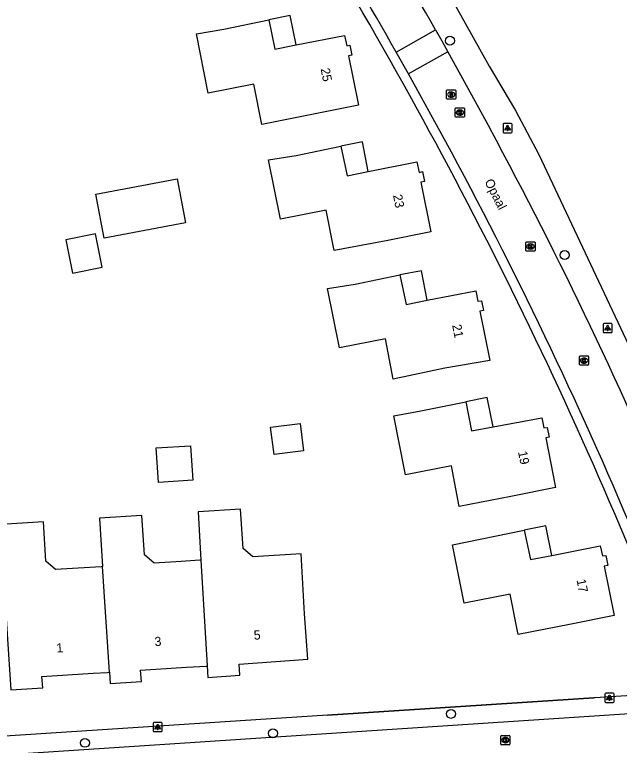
# Model space of a CAD drawing. Extents: x 159628 to 160723, y 388176 to 389416.
# Drawn here: x 160613.8 to 160680, y 388506.9 to 388586.9 of the extents above; entities that cross this region are included whole.
import ezdxf

# ---------------------------------------------------------------- set-up
doc = ezdxf.new("R2010")
doc.units = 0
for name, color, linetype in [('IMGEO_Boom', 7, 'Continuous'), ('IMGEO_Fietspad_gesloten', 7, 'Continuous'), ('IMGEO_Kolk', 7, 'Continuous'), ('IMGEO_Lichtpunt', 7, 'Continuous'), ('IMGEO_Muur', 7, 'Continuous'), ('IMGEO_Openbare_ruimte_label', 7, 'Continuous'), ('IMGEO_Pand', 7, 'Continuous'), ('IMGEO_Pand_nummerreeks', 7, 'Continuous'), ('IMGEO_Pand_overbouw', 7, 'Continuous'), ('IMGEO_Rijbaan_lokaal_open', 7, 'Continuous'), ('IMGEO_Rioolput', 7, 'Continuous'), ('IMGEO_Voetpad_open', 7, 'Continuous')]:
    doc.layers.add(name, color=color, linetype=linetype)

msp = doc.modelspace()

# ---------------------------------------------------------------- linework, layer by layer
at = {"layer": 'IMGEO_Boom'}
for centre in [(160661.403, 388584.05), (160673.966, 388560.586), (160661.517, 388510.38), (160642.034, 388508.252), (160621.458, 388507.209)]:
    msp.add_circle(centre, 0.489, dxfattribs=at)
at = {"layer": 'IMGEO_Fietspad_gesloten'}
msp.add_lwpolyline([(160617.404, 388655.77), (160618.348, 388654.532), (160644.11, 388617.805), (160648.439, 388610.479), (160651.047, 388606.571), (160653.72, 388602.158), (160659.741, 388591.966), (160665.707, 388581.259), (160668.575, 388576.406), (160671.137, 388571.605), (160689.88, 388531.792), (160696.248, 388516.722), (160696.73, 388515.639)], dxfattribs=at)
at = {"layer": 'IMGEO_Kolk'}
for p, q in [((160661.995, 388575.76), (160661.995, 388576.612)), ((160662.07, 388576.686), (160662.922, 388576.686)), ((160662.483, 388576.466), (160662.508, 388576.466)), ((160662.996, 388576.612), (160662.996, 388575.76)), ((160662.922, 388575.686), (160662.07, 388575.686)), ((160662.506, 388575.906), (160662.481, 388575.906)), ((160669.721, 388561.098), (160669.721, 388561.95)), ((160669.796, 388562.024), (160670.648, 388562.024)), ((160670.722, 388561.95), (160670.722, 388561.098)), ((160670.232, 388561.244), (160670.207, 388561.244)), ((160670.209, 388561.804), (160670.234, 388561.804)), ((160670.648, 388561.024), (160669.796, 388561.024)), ((160675.585, 388548.618), (160675.585, 388549.47)), ((160675.66, 388549.544), (160676.512, 388549.544)), ((160676.073, 388549.324), (160676.098, 388549.324)), ((160676.586, 388549.47), (160676.586, 388548.618)), ((160676.512, 388548.544), (160675.66, 388548.544)), ((160676.096, 388548.764), (160676.071, 388548.764)), ((160666.966, 388507.082), (160666.966, 388507.934)), ((160667.041, 388508.008), (160667.893, 388508.008)), ((160667.454, 388507.788), (160667.479, 388507.788)), ((160667.967, 388507.934), (160667.967, 388507.082)), ((160667.893, 388507.008), (160667.041, 388507.008)), ((160667.477, 388507.228), (160667.452, 388507.228))]:
    msp.add_line(p, q, dxfattribs=at)
for points in [[(160661.995, 388575.76), (160661.995, 388576.612)], [(160662.07, 388576.686), (160662.922, 388576.686)], [(160662.316, 388576.386), (160662.439, 388576.386), (160662.439, 388576.235), (160662.569, 388576.386), (160662.733, 388576.386), (160662.587, 388576.235), (160662.74, 388575.986), (160662.588, 388575.986), (160662.503, 388576.15), (160662.439, 388576.083), (160662.439, 388575.986), (160662.316, 388575.986), (160662.316, 388576.386)], [(160662.996, 388576.612), (160662.996, 388575.76)], [(160662.922, 388575.686), (160662.07, 388575.686)], [(160669.721, 388561.098), (160669.721, 388561.95)], [(160669.796, 388562.024), (160670.648, 388562.024)], [(160670.722, 388561.95), (160670.722, 388561.098)], [(160670.042, 388561.724), (160670.165, 388561.724), (160670.165, 388561.573), (160670.295, 388561.724), (160670.459, 388561.724), (160670.313, 388561.573), (160670.466, 388561.324), (160670.314, 388561.324), (160670.229, 388561.488), (160670.165, 388561.421), (160670.165, 388561.324), (160670.042, 388561.324), (160670.042, 388561.724)], [(160670.648, 388561.024), (160669.796, 388561.024)], [(160675.585, 388548.618), (160675.585, 388549.47)], [(160675.66, 388549.544), (160676.512, 388549.544)], [(160675.906, 388549.244), (160676.029, 388549.244), (160676.029, 388549.093), (160676.159, 388549.244), (160676.323, 388549.244), (160676.177, 388549.093), (160676.33, 388548.844), (160676.178, 388548.844), (160676.093, 388549.008), (160676.029, 388548.941), (160676.029, 388548.844), (160675.906, 388548.844), (160675.906, 388549.244)], [(160676.586, 388549.47), (160676.586, 388548.618)], [(160676.512, 388548.544), (160675.66, 388548.544)], [(160666.966, 388507.082), (160666.966, 388507.934)], [(160667.041, 388508.008), (160667.893, 388508.008)], [(160667.287, 388507.708), (160667.41, 388507.708), (160667.41, 388507.557), (160667.54, 388507.708), (160667.704, 388507.708), (160667.558, 388507.557), (160667.711, 388507.308), (160667.559, 388507.308), (160667.474, 388507.472), (160667.41, 388507.405), (160667.41, 388507.308), (160667.287, 388507.308), (160667.287, 388507.708)], [(160667.967, 388507.934), (160667.967, 388507.082)], [(160667.893, 388507.008), (160667.041, 388507.008)]]:
    msp.add_lwpolyline(points, dxfattribs=at)
for centre, start, end in [((160662.072, 388576.61), 91.55205, 178.44795), ((160662.072, 388576.61), 91.55205, 178.44795), ((160662.92, 388576.61), 1.55205, 88.44795), ((160662.92, 388576.61), 1.55205, 88.44795), ((160662.072, 388575.762), 181.55205, 268.44795), ((160662.072, 388575.762), 181.55205, 268.44795), ((160662.92, 388575.762), 271.55205, 358.44795), ((160662.92, 388575.762), 271.55205, 358.44795), ((160669.798, 388561.948), 91.55205, 178.44795), ((160669.798, 388561.948), 91.55205, 178.44795), ((160670.646, 388561.948), 1.55205, 88.44795), ((160670.646, 388561.948), 1.55205, 88.44795), ((160669.798, 388561.1), 181.55205, 268.44795), ((160669.798, 388561.1), 181.55205, 268.44795), ((160670.646, 388561.1), 271.55205, 358.44795), ((160670.646, 388561.1), 271.55205, 358.44795), ((160675.662, 388549.468), 91.55205, 178.44795), ((160675.662, 388549.468), 91.55205, 178.44795), ((160676.51, 388549.468), 1.55205, 88.44795), ((160676.51, 388549.468), 1.55205, 88.44795), ((160675.662, 388548.62), 181.55205, 268.44795), ((160675.662, 388548.62), 181.55205, 268.44795), ((160676.51, 388548.62), 271.55205, 358.44795), ((160676.51, 388548.62), 271.55205, 358.44795), ((160667.043, 388507.932), 91.55205, 178.44795), ((160667.043, 388507.932), 91.55205, 178.44795), ((160667.891, 388507.932), 1.55205, 88.44795), ((160667.891, 388507.932), 1.55205, 88.44795), ((160667.043, 388507.084), 181.55205, 268.44795), ((160667.043, 388507.084), 181.55205, 268.44795), ((160667.891, 388507.084), 271.55205, 358.44795), ((160667.891, 388507.084), 271.55205, 358.44795)]:
    msp.add_arc(centre, 0.0765, start, end, dxfattribs=at)
for centre, major_axis, ratio, start_param, end_param in [((160662.482, 388576.186), (-0.387, 0.002), 0.722429, 4.712389, 7.853982), ((160662.507, 388576.186), (-0.39, 0.002), 0.717154, 1.570796, 4.712389), ((160670.208, 388561.524), (-0.387, 0.002), 0.722429, 4.712389, 7.853982), ((160670.233, 388561.524), (-0.39, 0.002), 0.717154, 1.570796, 4.712389), ((160676.072, 388549.044), (-0.387, 0.002), 0.722429, 4.712389, 7.853982), ((160676.097, 388549.044), (-0.39, 0.002), 0.717154, 1.570796, 4.712389), ((160667.453, 388507.508), (-0.387, 0.002), 0.722429, 4.712389, 7.853982), ((160667.478, 388507.508), (-0.39, 0.002), 0.717154, 1.570796, 4.712389)]:
    msp.add_ellipse(centre, major_axis=major_axis, ratio=ratio, start_param=start_param, end_param=end_param, dxfattribs=at)
at = {"layer": 'IMGEO_Lichtpunt'}
for p, q in [((160667.216, 388574.882), (160667.216, 388574.075)), ((160667.216, 388574.882), (160667.216, 388574.075)), ((160668.118, 388574.977), (160667.31, 388574.977)), ((160668.118, 388574.977), (160667.31, 388574.977)), ((160668.212, 388574.075), (160668.212, 388574.882)), ((160668.212, 388574.075), (160668.212, 388574.882)), ((160667.31, 388573.981), (160668.118, 388573.981)), ((160667.31, 388573.981), (160668.118, 388573.981)), ((160679.073, 388553.1), (160678.265, 388553.1)), ((160679.073, 388553.1), (160678.265, 388553.1)), ((160678.171, 388553.005), (160678.171, 388552.198)), ((160678.171, 388553.005), (160678.171, 388552.198)), ((160679.167, 388552.198), (160679.167, 388553.005)), ((160679.167, 388552.198), (160679.167, 388553.005)), ((160678.265, 388552.104), (160679.073, 388552.104)), ((160678.265, 388552.104), (160679.073, 388552.104)), ((160678.367, 388512.533), (160678.367, 388511.726)), ((160678.367, 388512.533), (160678.367, 388511.726)), ((160679.269, 388512.628), (160678.461, 388512.628)), ((160679.269, 388512.628), (160678.461, 388512.628)), ((160679.363, 388511.726), (160679.363, 388512.533)), ((160679.363, 388511.726), (160679.363, 388512.533)), ((160678.461, 388511.632), (160679.269, 388511.632)), ((160678.461, 388511.632), (160679.269, 388511.632)), ((160628.924, 388509.337), (160628.924, 388508.53)), ((160628.924, 388509.337), (160628.924, 388508.53)), ((160629.826, 388509.432), (160629.018, 388509.432)), ((160629.826, 388509.432), (160629.018, 388509.432)), ((160629.92, 388508.53), (160629.92, 388509.337)), ((160629.92, 388508.53), (160629.92, 388509.337)), ((160629.018, 388508.436), (160629.826, 388508.436)), ((160629.018, 388508.436), (160629.826, 388508.436))]:
    msp.add_line(p, q, dxfattribs=at)
for points in [[(160667.59, 388574.546), (160667.629, 388574.518), (160667.441, 388574.256), (160667.403, 388574.283), (160667.59, 388574.546)], [(160667.692, 388574.498), (160667.739, 388574.498), (160667.739, 388574.176), (160667.692, 388574.176), (160667.692, 388574.498)], [(160667.802, 388574.518), (160667.84, 388574.545), (160668.027, 388574.283), (160667.988, 388574.255), (160667.802, 388574.518)], [(160678.545, 388552.669), (160678.584, 388552.641), (160678.396, 388552.379), (160678.358, 388552.406), (160678.545, 388552.669)], [(160678.647, 388552.621), (160678.694, 388552.621), (160678.694, 388552.299), (160678.647, 388552.299), (160678.647, 388552.621)], [(160678.757, 388552.641), (160678.795, 388552.668), (160678.982, 388552.406), (160678.943, 388552.378), (160678.757, 388552.641)], [(160678.741, 388512.197), (160678.78, 388512.169), (160678.592, 388511.907), (160678.554, 388511.934), (160678.741, 388512.197)], [(160678.843, 388512.149), (160678.89, 388512.149), (160678.89, 388511.827), (160678.843, 388511.827), (160678.843, 388512.149)], [(160678.953, 388512.169), (160678.991, 388512.196), (160679.178, 388511.934), (160679.139, 388511.906), (160678.953, 388512.169)], [(160629.298, 388509.001), (160629.337, 388508.973), (160629.149, 388508.711), (160629.111, 388508.738), (160629.298, 388509.001)], [(160629.4, 388508.953), (160629.447, 388508.953), (160629.447, 388508.631), (160629.4, 388508.631), (160629.4, 388508.953)], [(160629.51, 388508.973), (160629.548, 388509), (160629.735, 388508.738), (160629.696, 388508.71), (160629.51, 388508.973)]]:
    msp.add_lwpolyline(points, dxfattribs=at)
for centre in [(160667.715, 388574.68), (160678.67, 388552.803), (160678.866, 388512.331), (160629.423, 388509.135)]:
    msp.add_circle(centre, 0.0994, dxfattribs=at)
for centre, start, end in [((160667.31, 388574.882), 90, 180), ((160667.31, 388574.882), 90, 180), ((160668.118, 388574.882), 0, 90), ((160668.118, 388574.882), 0, 90), ((160667.31, 388574.075), 180, 270), ((160667.31, 388574.075), 180, 270), ((160668.118, 388574.075), 270, 0), ((160668.118, 388574.075), 270, 360), ((160678.265, 388553.005), 90, 180), ((160678.265, 388553.005), 90, 180), ((160679.073, 388553.005), 0, 90), ((160679.073, 388553.005), 0, 90), ((160678.265, 388552.198), 180, 270), ((160678.265, 388552.198), 180, 270), ((160679.073, 388552.198), 270, 0), ((160679.073, 388552.198), 270, 360), ((160678.461, 388512.533), 90, 180), ((160678.461, 388512.533), 90, 180), ((160679.269, 388512.533), 0, 90), ((160679.269, 388512.533), 0, 90), ((160678.461, 388511.726), 180, 270), ((160678.461, 388511.726), 180, 270), ((160679.269, 388511.726), 270, 0), ((160679.269, 388511.726), 270, 360), ((160629.018, 388509.337), 90, 180), ((160629.018, 388509.337), 90, 180), ((160629.826, 388509.337), 0, 90), ((160629.826, 388509.337), 0, 90), ((160629.018, 388508.53), 180, 270), ((160629.018, 388508.53), 180, 270), ((160629.826, 388508.53), 270, 0), ((160629.826, 388508.53), 270, 360)]:
    msp.add_arc(centre, 0.0946, start, end, dxfattribs=at)
at = {"layer": 'IMGEO_Muur'}
msp.add_lwpolyline([(160648.016, 388510.238), (160677.163, 388512.123)], dxfattribs=at)
at = {"layer": 'IMGEO_Pand'}
for points in [[(160646.491, 388576.008), (160640.824, 388574.888), (160639.948, 388579.304), (160634.944, 388578.311), (160633.658, 388584.787), (160636.68, 388585.304), (160641.57, 388586.346), (160642.256, 388583.128), (160644.574, 388583.58), (160649.858, 388584.611), (160650.11, 388583.493), (160650.464, 388583.541), (160650.679, 388582.473), (160650.313, 388582.397), (160651.396, 388576.975), (160646.491, 388576.008)], [(160647.866, 388565.509), (160642.86, 388564.529), (160641.552, 388570.993), (160644.587, 388571.499), (160649.481, 388572.521), (160650.16, 388569.272), (160652.463, 388569.729), (160657.779, 388570.785), (160658.041, 388569.63), (160658.4, 388569.717), (160658.611, 388568.63), (160658.231, 388568.553), (160659.316, 388563.147), (160654.415, 388562.161), (160648.731, 388561.091), (160647.866, 388565.509)], [(160622.659, 388567.255), (160631.546, 388568.935), (160632.458, 388564.104), (160623.572, 388562.425), (160622.659, 388567.255)], [(160620.115, 388558.604), (160623.35, 388559.265), (160622.604, 388562.918), (160619.369, 388562.258), (160620.115, 388558.604)], [(160651.041, 388557.391), (160655.935, 388558.413), (160656.61, 388555.183), (160658.924, 388555.636), (160664.232, 388556.676), (160664.471, 388555.532), (160664.849, 388555.597), (160665.066, 388554.539), (160664.695, 388554.445), (160665.767, 388549.04), (160660.838, 388548.204), (160655.206, 388546.992), (160654.339, 388551.409), (160649.333, 388550.426), (160648.026, 388556.912), (160651.041, 388557.391)], [(160663.133, 388544.528), (160663.774, 388541.342), (160666.14, 388541.789), (160671.449, 388542.791), (160671.682, 388541.68), (160672.047, 388541.73), (160672.258, 388540.651), (160671.895, 388540.574), (160672.975, 388535.152), (160668.072, 388534.173), (160662.427, 388533.091), (160661.562, 388537.51), (160656.553, 388536.53), (160655.285, 388542.99), (160658.232, 388543.542), (160663.133, 388544.528)], [(160641.786, 388541.752), (160645.022, 388542.156), (160645.393, 388539.183), (160642.156, 388538.779), (160641.786, 388541.752)], [(160629.27, 388539.48), (160633.024, 388539.722), (160633.268, 388535.953), (160629.513, 388535.711), (160629.27, 388539.48)], [(160634.833, 388515.62), (160634.906, 388514.366), (160638.418, 388514.61), (160638.339, 388515.837), (160645.838, 388516.351), (160645.497, 388521.34), (160645.131, 388527.893), (160639.827, 388527.554), (160638.765, 388528.488), (160638.491, 388532.785), (160633.851, 388532.484), (160634.159, 388527.193)], [(160634.159, 388527.193), (160634.033, 388527.185), (160631.983, 388527.053), (160629.044, 388526.863), (160627.981, 388527.796), (160627.704, 388532.087), (160623.054, 388531.786), (160623.396, 388526.497)], [(160623.396, 388526.497), (160623.236, 388526.487), (160618.868, 388526.205), (160618.256, 388526.165), (160617.193, 388527.098), (160616.916, 388531.389), (160612.242, 388531.087)], [(160669.546, 388530.489), (160670.211, 388527.262), (160672.57, 388527.729), (160677.854, 388528.775), (160678.092, 388527.68), (160678.458, 388527.701), (160678.678, 388526.63), (160678.293, 388526.549), (160679.386, 388521.137), (160674.482, 388520.155), (160668.857, 388519.051), (160667.991, 388523.484), (160662.967, 388522.502), (160661.691, 388528.87), (160669.546, 388530.489)], [(160634.159, 388527.193), (160634.833, 388515.62)], [(160624.144, 388514.933), (160623.396, 388526.497)], [(160612.793, 388521.346), (160613.018, 388517.996), (160613.348, 388513.006), (160616.84, 388513.237), (160616.735, 388514.453), (160622.367, 388514.818), (160623.943, 388514.92), (160624.144, 388514.933)], [(160624.144, 388514.933), (160624.224, 388513.704), (160627.638, 388513.913), (160627.557, 388515.168), (160632.568, 388515.479), (160634.749, 388515.615), (160634.833, 388515.62)]]:
    msp.add_lwpolyline(points, dxfattribs=at)
at = {"layer": 'IMGEO_Pand_overbouw'}
for points in [[(160644.574, 388583.58), (160643.925, 388586.811), (160641.57, 388586.346), (160642.256, 388583.128)], [(160652.463, 388569.729), (160651.839, 388572.985), (160649.481, 388572.521), (160650.16, 388569.272)], [(160655.935, 388558.413), (160656.61, 388555.183), (160658.924, 388555.636), (160658.288, 388558.879)], [(160666.14, 388541.789), (160665.496, 388544.997), (160663.133, 388544.528), (160663.774, 388541.342)], [(160672.57, 388527.729), (160671.905, 388530.953), (160669.546, 388530.489), (160670.211, 388527.262)]]:
    msp.add_lwpolyline(points, close=True, dxfattribs=at)
at = {"layer": 'IMGEO_Rijbaan_lokaal_open'}
for points in [[(160655.528, 388582.803), (160659.827, 388585.236)], [(160659.827, 388585.236), (160660.507, 388584.03), (160661.184, 388582.823)], [(160656.874, 388580.411), (160655.528, 388582.803)], [(160661.184, 388582.823), (160656.874, 388580.411)], [(160661.184, 388582.823), (160665.773, 388574.47)], [(160661.572, 388571.858), (160656.874, 388580.411)], [(160601.875, 388505.15), (160610.788, 388505.771), (160685.519, 388510.699)]]:
    msp.add_lwpolyline(points, dxfattribs=at)
for centre, radius, start, end in [((160131.083, 388286.162), 607.466, 29.493811, 32.869723), ((160131.433, 388286.289), 602.16, 29.499633, 32.79812), ((160245.588, 388347.41), 477.61, 22.54147, 28.38593), ((160222.087, 388336.171), 498.694, 22.67051, 28.20378)]:
    msp.add_arc(centre, radius, start, end, dxfattribs=at)
at = {"layer": 'IMGEO_Rioolput'}
for p, q in [((160661.122, 388578.655), (160661.974, 388578.655)), ((160661.047, 388577.729), (160661.047, 388578.581)), ((160661.558, 388577.875), (160661.533, 388577.875)), ((160661.535, 388578.435), (160661.56, 388578.435)), ((160662.048, 388578.581), (160662.048, 388577.729)), ((160661.974, 388577.655), (160661.122, 388577.655))]:
    msp.add_line(p, q, dxfattribs=at)
for points in [[(160661.122, 388578.655), (160661.974, 388578.655)], [(160661.047, 388577.729), (160661.047, 388578.581)], [(160661.636, 388578.353), (160661.384, 388578.355), (160661.384, 388577.955)], [(160661.384, 388577.955), (160661.508, 388577.955), (160661.508, 388578.117), (160661.519, 388578.117)], [(160661.562, 388578.274), (160661.508, 388578.274), (160661.508, 388578.193)], [(160661.508, 388578.193), (160661.56, 388578.193)], [(160661.566, 388578.088), (160661.637, 388577.955), (160661.777, 388577.955), (160661.712, 388578.081)], [(160662.048, 388578.581), (160662.048, 388577.729)], [(160661.974, 388577.655), (160661.122, 388577.655)]]:
    msp.add_lwpolyline(points, dxfattribs=at)
for centre, radius, start, end in [((160661.124, 388578.579), 0.0765, 91.55205, 178.44795), ((160661.124, 388578.579), 0.0765, 91.55205, 178.44795), ((160661.972, 388578.579), 0.0765, 1.55205, 88.44795), ((160661.972, 388578.579), 0.0765, 1.55205, 88.44795), ((160661.518, 388578.064), 0.0533, 26.02933, 88.69889), ((160661.544, 388578.382), 0.19, 274.7715, 282.96867), ((160661.568, 388578.178), 0.0964, 77.00612, 93.18647), ((160661.582, 388578.235), 0.0378, 276.66336, 79.67722), ((160661.635, 388578.243), 0.109, 350.36119, 89.41601), ((160661.633, 388578.243), 0.112, 277.58423, 350.98172), ((160661.617, 388578.028), 0.108, 29.51342, 73.79051), ((160661.124, 388577.731), 0.0765, 181.55205, 268.44795), ((160661.124, 388577.731), 0.0765, 181.55205, 268.44795), ((160661.972, 388577.731), 0.0765, 271.55205, 358.44795), ((160661.972, 388577.731), 0.0765, 271.55205, 358.44795)]:
    msp.add_arc(centre, radius, start, end, dxfattribs=at)
for centre, major_axis, ratio, start_param, end_param in [((160661.534, 388578.155), (-0.387, 0.002), 0.722429, 4.712389, 7.853982), ((160661.559, 388578.155), (-0.39, 0.002), 0.717154, 1.570796, 4.712389)]:
    msp.add_ellipse(centre, major_axis=major_axis, ratio=ratio, start_param=start_param, end_param=end_param, dxfattribs=at)
at = {"layer": 'IMGEO_Voetpad_open'}
msp.add_lwpolyline([(160685.353, 388512.651), (160677.276, 388512.131), (160677.163, 388512.123), (160648.016, 388510.238), (160609.875, 388507.771)], dxfattribs=at)
for centre, radius, start, end in [((160136.463, 388289.389), 595.224, 28.296796, 32.866288), ((160219.268, 388335.128), 500.633, 22.66484, 28.17992)]:
    msp.add_arc(centre, radius, start, end, dxfattribs=at)

# ---------------------------------------------------------------- texts
at = {"layer": 'IMGEO_Openbare_ruimte_label'}
msp.add_text('Opaal', height=1, rotation=296.79556, dxfattribs=at).set_placement((160665.17, 388568.623))
at = {"layer": 'IMGEO_Pand_nummerreeks'}
for s, rotation, p in [('25', 281.38783, (160647.249, 388580.955)), ('23', 281.37772, (160655.169, 388567.129)), ('21', 281.3662, (160661.643, 388552.91)), ('19', 281.29695, (160668.851, 388539.049)), ('17', 281.34166, (160675.26, 388525.032)), ('5', 3.72996, (160639.971, 388518.494)), ('3', 3.72996, (160629.114, 388517.787)), ('1', 3.72996, (160618.371, 388517.086))]:
    msp.add_text(s, height=1, rotation=rotation, dxfattribs=at).set_placement(p)

doc.saveas('drawing.dxf')
